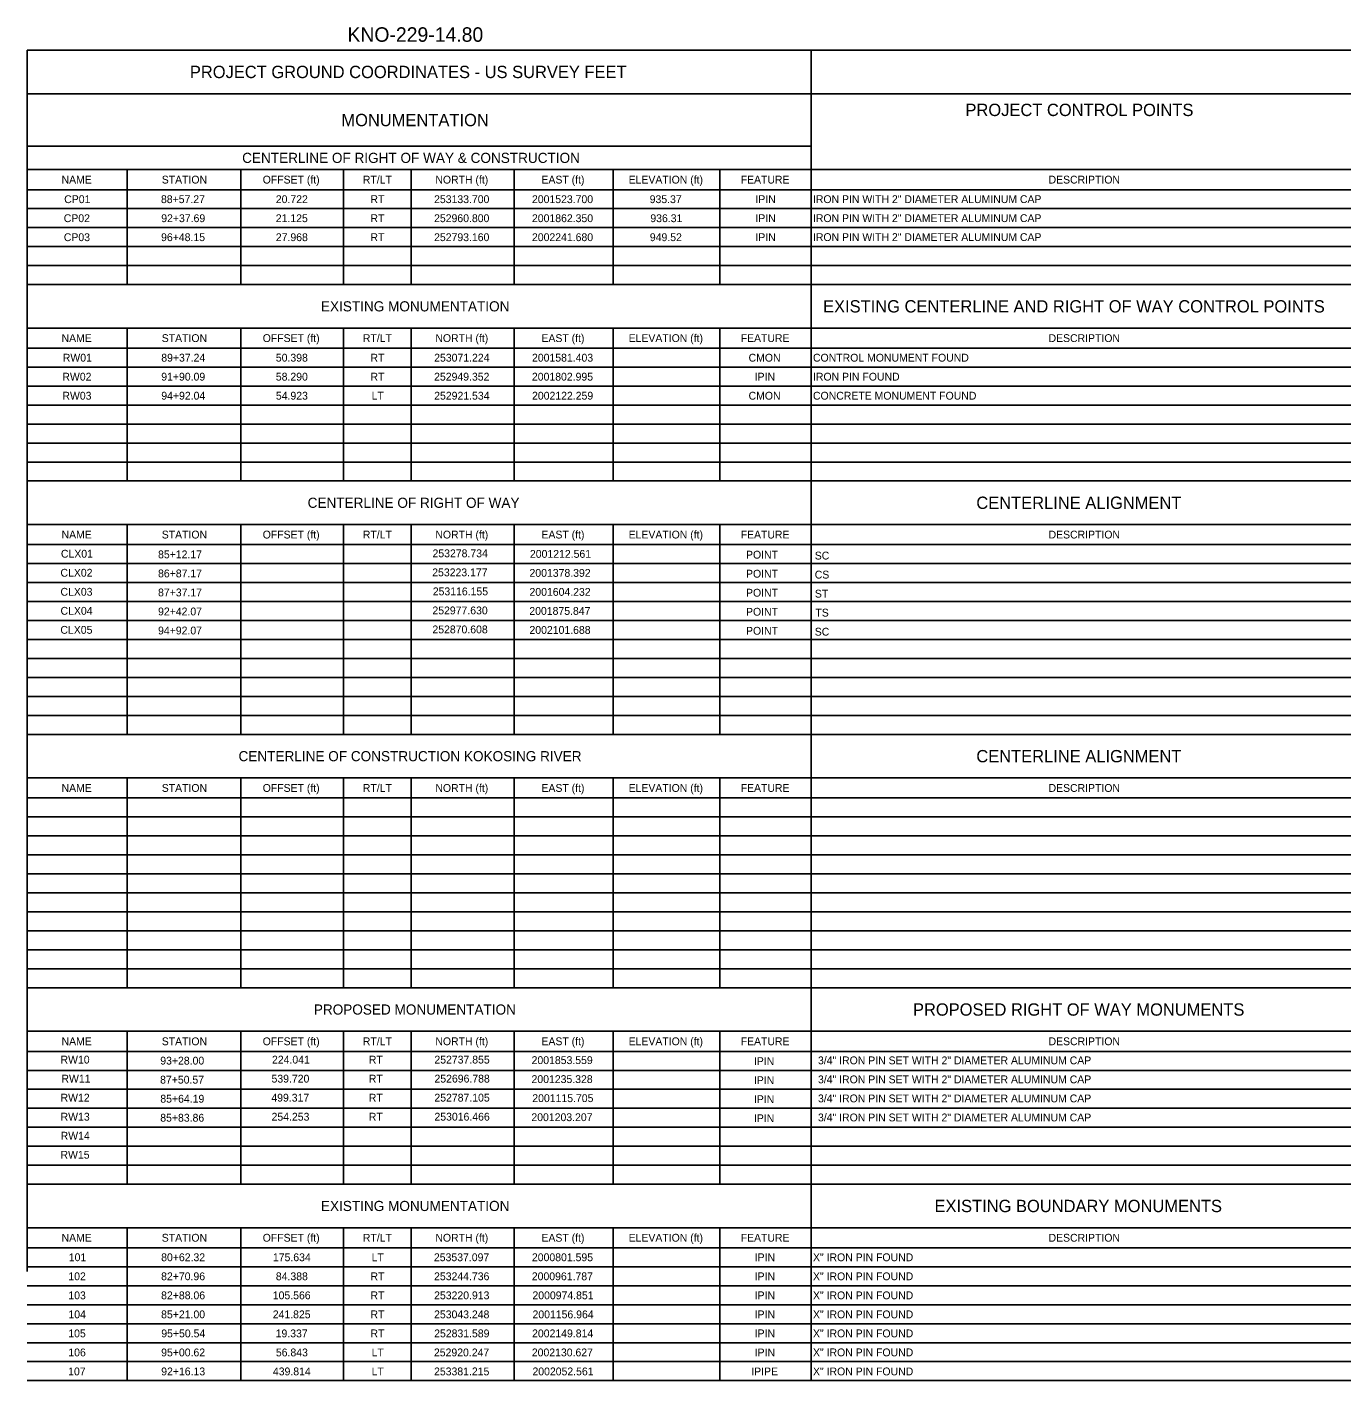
# Model space of a CAD drawing. Extents: x -4451 to 6119, y -1533 to 848.
# Drawn here: x 30.1 to 392.9, y 474.5 to 848.1 of the extents above; entities that cross this region are included whole.
import ezdxf

# ---------------------------------------------------------------- set-up
doc = ezdxf.new("R2010")
doc.units = 0
doc.layers.add('SC_Scratch1', color=7, linetype='Continuous')

msp = doc.modelspace()

# ---------------------------------------------------------------- linework, layer by layer
at = {"layer": 'SC_Scratch1'}
for p, q in [((30.12, 841.7), (640.12, 841.7)), ((30.12, 504.77), (30.12, 841.7)), ((246.43, 474.54), (246.43, 841.7)), ((30.12, 829.69), (246.43, 829.69)), ((246.43, 829.69), (397.85, 829.69)), ((30.12, 815.21), (246.43, 815.21)), ((30.12, 808.75), (579.55, 808.75)), ((57.7, 777.03), (57.7, 808.75)), ((89.07, 777.03), (89.07, 808.75)), ((117.46, 777.03), (117.46, 808.75)), ((136.11, 777.03), (136.11, 808.75)), ((164.51, 777.03), (164.51, 808.75)), ((191.81, 777.03), (191.81, 808.75)), ((221.29, 777.03), (221.29, 808.75)), ((30.12, 803.2), (246.43, 803.2)), ((246.43, 803.2), (640.12, 803.2)), ((30.12, 797.97), (640.12, 797.97)), ((30.12, 792.73), (640.12, 792.73)), ((30.12, 787.5), (640.12, 787.5)), ((30.12, 782.26), (640.12, 782.26)), ((30.12, 777.03), (640.12, 777.03)), ((30.12, 765.02), (579.55, 765.02)), ((57.7, 722.83), (57.7, 765.02)), ((89.07, 722.79), (89.07, 765.02)), ((117.46, 722.83), (117.46, 765.02)), ((136.11, 722.82), (136.11, 765.02)), ((164.51, 722.85), (164.51, 765.02)), ((191.81, 722.83), (191.81, 765.02)), ((221.29, 722.85), (221.29, 765.02)), ((30.12, 759.47), (640.12, 759.47)), ((30.12, 754.24), (640.12, 754.24)), ((30.12, 749), (640.12, 749)), ((30.12, 743.77), (640.12, 743.77)), ((30.12, 738.53), (640.12, 738.53)), ((30.12, 733.3), (640.12, 733.3)), ((30.12, 728.06), (640.12, 728.06)), ((30.12, 722.83), (640.12, 722.83)), ((30.12, 722.83), (640.12, 722.83)), ((30.12, 710.82), (579.55, 710.82)), ((57.7, 652.93), (57.7, 710.82)), ((89.07, 652.93), (89.07, 710.82)), ((117.46, 652.99), (117.46, 710.82)), ((136.11, 652.96), (136.11, 710.82)), ((164.51, 652.96), (164.51, 710.82)), ((191.81, 652.96), (191.81, 710.82)), ((221.29, 652.96), (221.29, 710.82)), ((30.12, 705.27), (640.12, 705.27)), ((30.12, 700.04), (640.12, 700.04)), ((30.12, 694.8), (640.12, 694.8)), ((30.12, 689.57), (640.12, 689.57)), ((30.12, 684.33), (640.12, 684.33)), ((30.12, 679.1), (640.12, 679.1)), ((30.12, 673.86), (640.12, 673.86)), ((30.12, 668.63), (640.12, 668.63)), ((30.12, 663.39), (640.12, 663.39)), ((30.12, 658.16), (640.12, 658.16)), ((30.12, 652.92), (640.12, 652.92)), ((30.12, 652.92), (640.12, 652.92)), ((30.12, 652.92), (640.12, 652.92)), ((30.12, 640.91), (579.55, 640.91)), ((57.7, 583.03), (57.7, 640.91)), ((89.07, 583.02), (89.07, 640.91)), ((117.46, 583.09), (117.46, 640.91)), ((136.11, 583.06), (136.11, 640.91)), ((164.51, 583.06), (164.51, 640.91)), ((191.81, 583.06), (191.81, 640.91)), ((221.29, 583.06), (221.29, 640.91)), ((30.12, 635.37), (640.12, 635.37)), ((30.12, 630.14), (640.12, 630.14)), ((30.12, 624.9), (640.12, 624.9)), ((30.12, 619.67), (640.12, 619.67)), ((30.12, 614.43), (640.12, 614.43)), ((30.12, 609.2), (640.12, 609.2)), ((30.12, 603.96), (640.12, 603.96)), ((30.12, 598.73), (640.12, 598.73)), ((30.12, 593.49), (640.12, 593.49)), ((30.12, 588.25), (640.12, 588.25)), ((30.12, 583.02), (640.12, 583.02)), ((30.12, 583.02), (640.12, 583.02)), ((30.12, 571.01), (579.55, 571.01)), ((57.7, 528.82), (57.7, 571.01)), ((89.07, 528.79), (89.07, 571.01)), ((117.46, 528.82), (117.46, 571.01)), ((136.11, 528.81), (136.11, 571.01)), ((164.51, 528.85), (164.51, 571.01)), ((191.81, 528.82), (191.81, 571.01)), ((221.29, 528.84), (221.29, 571.01)), ((30.12, 565.47), (640.12, 565.47)), ((30.12, 560.23), (640.12, 560.23)), ((30.12, 555), (640.12, 555)), ((30.12, 549.76), (640.12, 549.76)), ((30.12, 544.53), (640.12, 544.53)), ((30.12, 539.29), (640.12, 539.29)), ((30.12, 534.06), (640.12, 534.06)), ((30.12, 528.82), (640.12, 528.82)), ((30.12, 528.82), (640.12, 528.82)), ((30.12, 528.82), (640.12, 528.82)), ((30.12, 516.81), (579.55, 516.81)), ((57.7, 474.62), (57.7, 516.81)), ((89.07, 474.59), (89.07, 516.81)), ((117.46, 474.62), (117.46, 516.81)), ((136.11, 474.62), (136.11, 516.81)), ((164.51, 474.65), (164.51, 516.81)), ((191.81, 474.63), (191.81, 516.81)), ((221.29, 474.64), (221.29, 516.81)), ((30.12, 511.27), (640.12, 511.27)), ((30.12, 506.03), (640.12, 506.03)), ((30.12, 500.8), (640.12, 500.8)), ((30.12, 495.56), (640.12, 495.56)), ((30.12, 490.33), (640.12, 490.33)), ((30.12, 485.09), (640.12, 485.09)), ((30.12, 479.86), (640.12, 479.86)), ((30.12, 474.62), (640.12, 474.62)), ((30.12, 474.62), (640.12, 474.62))]:
    msp.add_line(p, q, dxfattribs=at)

# ---------------------------------------------------------------- texts
for s, height, p in [('KNO-229-14.80', 4, (118.52, 844.01)), ('PROJECT GROUND COORDINATES - US SURVEY FEET', 3.4, (75.04, 833.99)), ('PROJECT CONTROL POINTS', 3.4, (289.04, 823.52)), ('MONUMENTATION ', 3.4, (116.85, 820.72)), ('CENTERLINE OF RIGHT OF WAY & CONSTRUCTION', 2.8, (89.47, 810.58)), ('NAME', 2.157, (39.64, 804.9)), ('STATION', 2.157, (67.28, 804.9)), ('OFFSET (ft)', 2.1565, (95.14, 804.9)), ('RT/LT', 2.157, (122.77, 804.9)), ('NORTH (ft)', 2.157, (142.78, 804.9)), ('EAST (ft)', 2.157, (172.05, 804.9)), ('ELEVATION (ft)', 2.1565, (196.11, 804.9)), ('FEATURE', 2.157, (227.02, 804.9)), ('DESCRIPTION', 2.1565, (311.97, 804.9)), ('CP01', 2.16, (40.37, 799.5)), ('88+57.27', 2.16, (67.07, 799.5)), ('20.722', 2.16, (98.76, 799.5)), ('RT', 2.16, (124.87, 799.5)), ('253133.700', 2.16, (142.42, 799.5)), ('2001523.700', 2.16, (169.43, 799.5)), ('935.37', 2.16, (201.91, 799.5)), ('IPIN', 2.16, (231.08, 799.5)), ('IRON PIN WITH 2" DIAMETER ALUMINUM CAP', 2.1565, (246.97, 799.51)), ('CP02', 2.16, (40.25, 794.25)), ('92+37.69', 2.16, (67.14, 794.25)), ('21.125', 2.16, (98.75, 794.25)), ('RT', 2.16, (124.87, 794.25)), ('252960.800', 2.16, (142.42, 794.25)), ('2001862.350', 2.16, (169.43, 794.25)), ('936.31', 2.16, (202.09, 794.25)), ('IPIN', 2.16, (231.08, 794.25)), ('IRON PIN WITH 2" DIAMETER ALUMINUM CAP', 2.1565, (246.97, 794.27)), ('CP03', 2.16, (40.26, 789.01)), ('96+48.15', 2.16, (67.1, 789.01)), ('27.968', 2.16, (98.76, 789.01)), ('RT', 2.16, (124.87, 789.01)), ('252793.160', 2.16, (142.42, 789.01)), ('2002241.680', 2.16, (169.43, 789.01)), ('949.52', 2.16, (201.96, 789.01)), ('IPIN', 2.16, (231.08, 789.01)), ('IRON PIN WITH 2" DIAMETER ALUMINUM CAP', 2.1565, (246.97, 789.04)), ('EXISTING MONUMENTATION', 2.8, (111.21, 769.62)), ('EXISTING CENTERLINE AND RIGHT OF WAY CONTROL POINTS', 3.4, (249.75, 769.32)), ('NAME', 2.157, (39.64, 761.17)), ('STATION', 2.157, (67.28, 761.17)), ('OFFSET (ft)', 2.1565, (95.14, 761.17)), ('RT/LT', 2.157, (122.77, 761.17)), ('NORTH (ft)', 2.157, (142.78, 761.17)), ('EAST (ft)', 2.157, (172.05, 761.17)), ('ELEVATION (ft)', 2.1565, (196.11, 761.17)), ('FEATURE', 2.157, (227.02, 761.17)), ('DESCRIPTION', 2.1565, (311.97, 761.17)), ('RW01', 2.16, (39.98, 755.77)), ('89+37.24', 2.16, (67.15, 755.77)), ('50.398', 2.16, (98.76, 755.77)), ('RT', 2.16, (124.87, 755.77)), ('253071.224', 2.16, (142.45, 755.77)), ('2001581.403', 2.16, (169.44, 755.77)), ('CMON', 2.16, (229.2, 755.77)), ('CONTROL MONUMENT FOUND', 2.16, (246.97, 755.77)), ('RW02', 2.16, (39.86, 750.53)), ('91+90.09', 2.16, (67.14, 750.53)), ('58.290', 2.16, (98.76, 750.53)), ('RT', 2.16, (124.87, 750.53)), ('252949.352', 2.16, (142.43, 750.53)), ('2001802.995', 2.16, (169.42, 750.53)), ('IPIN', 2.16, (230.88, 750.53)), ('IRON PIN FOUND ', 2.16, (246.97, 750.53)), ('RW03', 2.16, (39.87, 745.28)), ('94+92.04', 2.16, (67.15, 745.28)), ('54.923', 2.16, (98.77, 745.28)), ('LT', 2.16, (125.2, 745.28)), ('252921.534', 2.16, (142.45, 745.28)), ('2002122.259', 2.16, (169.45, 745.28)), ('CMON', 2.16, (229.2, 745.28)), ('CONCRETE MONUMENT FOUND', 2.16, (246.97, 745.28)), ('CENTERLINE OF RIGHT OF WAY ', 2.8, (107.54, 715.42)), ('CENTERLINE ALIGNMENT', 3.4, (292.04, 715.12)), ('NAME', 2.157, (39.64, 706.97)), ('STATION', 2.157, (67.28, 706.97)), ('OFFSET (ft)', 2.1565, (95.14, 706.97)), ('RT/LT', 2.157, (122.77, 706.97)), ('NORTH (ft)', 2.157, (142.78, 706.97)), ('EAST (ft)', 2.157, (172.05, 706.97)), ('ELEVATION (ft)', 2.1565, (196.11, 706.97)), ('FEATURE', 2.157, (227.02, 706.97)), ('DESCRIPTION', 2.1565, (311.97, 706.97)), ('CLX01', 2.16, (39.46, 701.68)), ('85+12.17', 2.16, (66.26, 701.5)), ('253278.734', 2.16, (141.99, 701.79)), ('2001212.561', 2.16, (168.87, 701.64)), ('POINT', 2.16, (228.49, 701.42)), ('SC', 2.16, (247.46, 701.17)), ('CLX02', 2.16, (39.34, 696.43)), ('253223.177', 2.16, (141.91, 696.54)), ('2001378.392', 2.16, (168.75, 696.39)), ('86+87.17', 2.16, (66.26, 696.25)), ('POINT', 2.16, (228.49, 696.17)), ('CS', 2.16, (247.46, 695.92)), ('CLX03', 2.16, (39.34, 691.18)), ('87+37.17', 2.16, (66.26, 691)), ('253116.155', 2.16, (142.06, 691.29)), ('2001604.232', 2.16, (168.75, 691.15)), ('POINT', 2.16, (228.49, 690.92)), ('ST', 2.16, (247.49, 690.67)), ('CLX04', 2.16, (39.36, 685.93)), ('92+42.07', 2.16, (66.26, 685.75)), ('252977.630', 2.16, (141.96, 686.04)), ('2001875.847', 2.16, (168.7, 685.9)), ('POINT', 2.16, (228.49, 685.67)), ('TS', 2.16, (247.63, 685.42)), ('CLX05', 2.16, (39.32, 680.68)), ('94+92.07', 2.16, (66.26, 680.5)), ('252870.608', 2.16, (141.96, 680.8)), ('2002101.688', 2.16, (168.74, 680.65)), ('POINT', 2.16, (228.49, 680.42)), ('SC', 2.16, (247.46, 680.17)), ('CENTERLINE OF CONSTRUCTION KOKOSING RIVER', 2.8, (88.46, 645.51)), ('CENTERLINE ALIGNMENT', 3.4, (292.04, 645.21)), ('NAME', 2.157, (39.64, 637.06)), ('STATION', 2.157, (67.28, 637.06)), ('OFFSET (ft)', 2.1565, (95.14, 637.06)), ('RT/LT', 2.157, (122.77, 637.06)), ('NORTH (ft)', 2.157, (142.78, 637.06)), ('EAST (ft)', 2.157, (172.05, 637.06)), ('ELEVATION (ft)', 2.1565, (196.11, 637.06)), ('FEATURE', 2.157, (227.02, 637.06)), ('DESCRIPTION', 2.1565, (311.97, 637.06)), ('PROPOSED MONUMENTATION', 2.8, (109.25, 575.61)), ('PROPOSED RIGHT OF WAY MONUMENTS', 3.4, (274.56, 575.31)), ('NAME', 2.157, (39.64, 567.16)), ('STATION', 2.157, (67.28, 567.16)), ('OFFSET (ft)', 2.1565, (95.14, 567.16)), ('RT/LT', 2.157, (122.77, 567.16)), ('NORTH (ft)', 2.157, (142.78, 567.16)), ('EAST (ft)', 2.157, (172.05, 567.16)), ('ELEVATION (ft)', 2.1565, (196.11, 567.16)), ('FEATURE', 2.157, (227.02, 567.16)), ('DESCRIPTION', 2.1565, (311.97, 567.16)), ('RW10', 2.16, (39.35, 562.1)), ('224.041', 2.16, (97.7, 562.1)), ('RT', 2.16, (124.41, 562.1)), ('252737.855', 2.16, (142.51, 562.11)), ('2001853.559', 2.16, (169.33, 561.96)), ('3/4" IRON PIN SET WITH 2" DIAMETER ALUMINUM CAP', 2.16, (248.35, 561.9)), ('93+28.00', 2.16, (66.87, 561.82)), ('IPIN', 2.16, (230.67, 561.68)), ('RW11', 2.16, (39.6, 556.86)), ('87+50.57', 2.16, (66.83, 556.57)), ('539.720', 2.16, (97.57, 556.85)), ('RT', 2.16, (124.41, 556.85)), ('252696.788', 2.16, (142.53, 556.86)), ('2001235.328', 2.16, (169.31, 556.72)), ('IPIN', 2.16, (230.67, 556.43)), ('3/4" IRON PIN SET WITH 2" DIAMETER ALUMINUM CAP', 2.16, (248.35, 556.65)), ('RW12', 2.16, (39.36, 551.61)), ('85+64.19', 2.16, (66.89, 551.32)), ('499.317', 2.16, (97.52, 551.6)), ('RT', 2.16, (124.41, 551.6)), ('252787.105', 2.16, (142.51, 551.61)), ('2001115.705', 2.16, (169.52, 551.47)), ('IPIN', 2.16, (230.67, 551.18)), ('3/4" IRON PIN SET WITH 2" DIAMETER ALUMINUM CAP', 2.16, (248.35, 551.4)), ('RW13', 2.16, (39.37, 546.36)), ('85+83.86', 2.16, (66.87, 546.07)), ('254.253', 2.16, (97.58, 546.35)), ('RT', 2.16, (124.41, 546.35)), ('253016.466', 2.16, (142.52, 546.36)), ('2001203.207', 2.16, (169.27, 546.22)), ('IPIN', 2.16, (230.67, 545.93)), ('3/4" IRON PIN SET WITH 2" DIAMETER ALUMINUM CAP', 2.16, (248.35, 546.15)), ('RW14', 2.16, (39.39, 541.11)), ('RW15', 2.16, (39.34, 535.86)), ('EXISTING MONUMENTATION', 2.8, (111.21, 521.41)), ('EXISTING BOUNDARY MONUMENTS ', 3.4, (280.5, 521.11)), ('NAME', 2.157, (39.64, 512.96)), ('STATION', 2.157, (67.28, 512.96)), ('OFFSET (ft)', 2.1565, (95.14, 512.96)), ('RT/LT', 2.157, (122.77, 512.96)), ('NORTH (ft)', 2.157, (142.78, 512.96)), ('EAST (ft)', 2.157, (172.05, 512.96)), ('ELEVATION (ft)', 2.1565, (196.11, 512.96)), ('FEATURE', 2.157, (227.02, 512.96)), ('DESCRIPTION', 2.1565, (311.97, 512.96)), ('101', 2.16, (41.63, 507.57)), ('80+62.32', 2.16, (67.12, 507.57)), ('175.634', 2.16, (97.95, 507.57)), ('LT', 2.16, (125.2, 507.57)), ('253537.097', 2.16, (142.38, 507.57)), ('2000801.595', 2.16, (169.42, 507.57)), ('IPIN', 2.16, (230.88, 507.57)), ('X" IRON PIN FOUND ', 2.16, (246.97, 507.57)), ('102', 2.16, (41.51, 502.32)), ('82+70.96', 2.16, (67.11, 502.32)), ('84.388', 2.16, (98.76, 502.32)), ('RT', 2.16, (124.87, 502.32)), ('253244.736', 2.16, (142.42, 502.32)), ('2000961.787', 2.16, (169.39, 502.32)), ('IPIN', 2.16, (230.88, 502.32)), ('X" IRON PIN FOUND ', 2.16, (246.97, 502.32)), ('103', 2.16, (41.51, 497.07)), ('82+88.06', 2.16, (67.11, 497.07)), ('105.566', 2.16, (97.92, 497.07)), ('RT', 2.16, (124.87, 497.07)), ('253220.913', 2.16, (142.43, 497.07)), ('2000974.851', 2.16, (169.56, 497.07)), ('IPIN', 2.16, (230.88, 497.07)), ('X" IRON PIN FOUND ', 2.16, (246.97, 497.07)), ('104', 2.16, (41.53, 491.82)), ('85+21.00', 2.16, (67.11, 491.82)), ('241.825', 2.16, (97.91, 491.82)), ('RT', 2.16, (124.87, 491.82)), ('253043.248', 2.16, (142.42, 491.82)), ('2001156.964', 2.16, (169.58, 491.82)), ('IPIN', 2.16, (230.88, 491.82)), ('X" IRON PIN FOUND ', 2.16, (246.97, 491.82)), ('105', 2.16, (41.49, 486.57)), ('95+50.54', 2.16, (67.15, 486.57)), ('19.337', 2.16, (98.71, 486.57)), ('RT', 2.16, (124.87, 486.57)), ('252831.589', 2.16, (142.44, 486.57)), ('2002149.814', 2.16, (169.46, 486.57)), ('IPIN', 2.16, (230.88, 486.57)), ('X" IRON PIN FOUND ', 2.16, (246.97, 486.57)), ('106', 2.16, (41.5, 481.32)), ('95+00.62', 2.16, (67.12, 481.32)), ('56.843', 2.16, (98.77, 481.32)), ('LT', 2.16, (125.2, 481.32)), ('252920.247', 2.16, (142.38, 481.32)), ('2002130.627', 2.16, (169.39, 481.32)), ('IPIN', 2.16, (230.88, 481.32)), ('X" IRON PIN FOUND ', 2.16, (246.97, 481.33)), ('107', 2.16, (41.46, 476.08)), ('92+16.13', 2.16, (67.13, 476.08)), ('439.814', 2.16, (97.95, 476.08)), ('LT', 2.16, (125.2, 476.08)), ('253381.215', 2.16, (142.41, 476.08)), ('2002052.561', 2.16, (169.56, 476.08)), ('IPIPE', 2.16, (229.93, 476.08)), ('X" IRON PIN FOUND ', 2.16, (246.97, 476.08))]:
    msp.add_text(s, height=height, dxfattribs=at).set_placement(p)

doc.saveas('drawing.dxf')
